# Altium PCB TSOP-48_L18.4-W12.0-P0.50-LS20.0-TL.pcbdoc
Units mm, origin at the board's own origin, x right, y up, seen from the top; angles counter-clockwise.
Board outline 33.53 x 25.28 mm, 2 copper layers (Top Layer, Bottom Layer), stack 0 mm thick; 1 components, 0 nets, 48 pads, 0 vias.
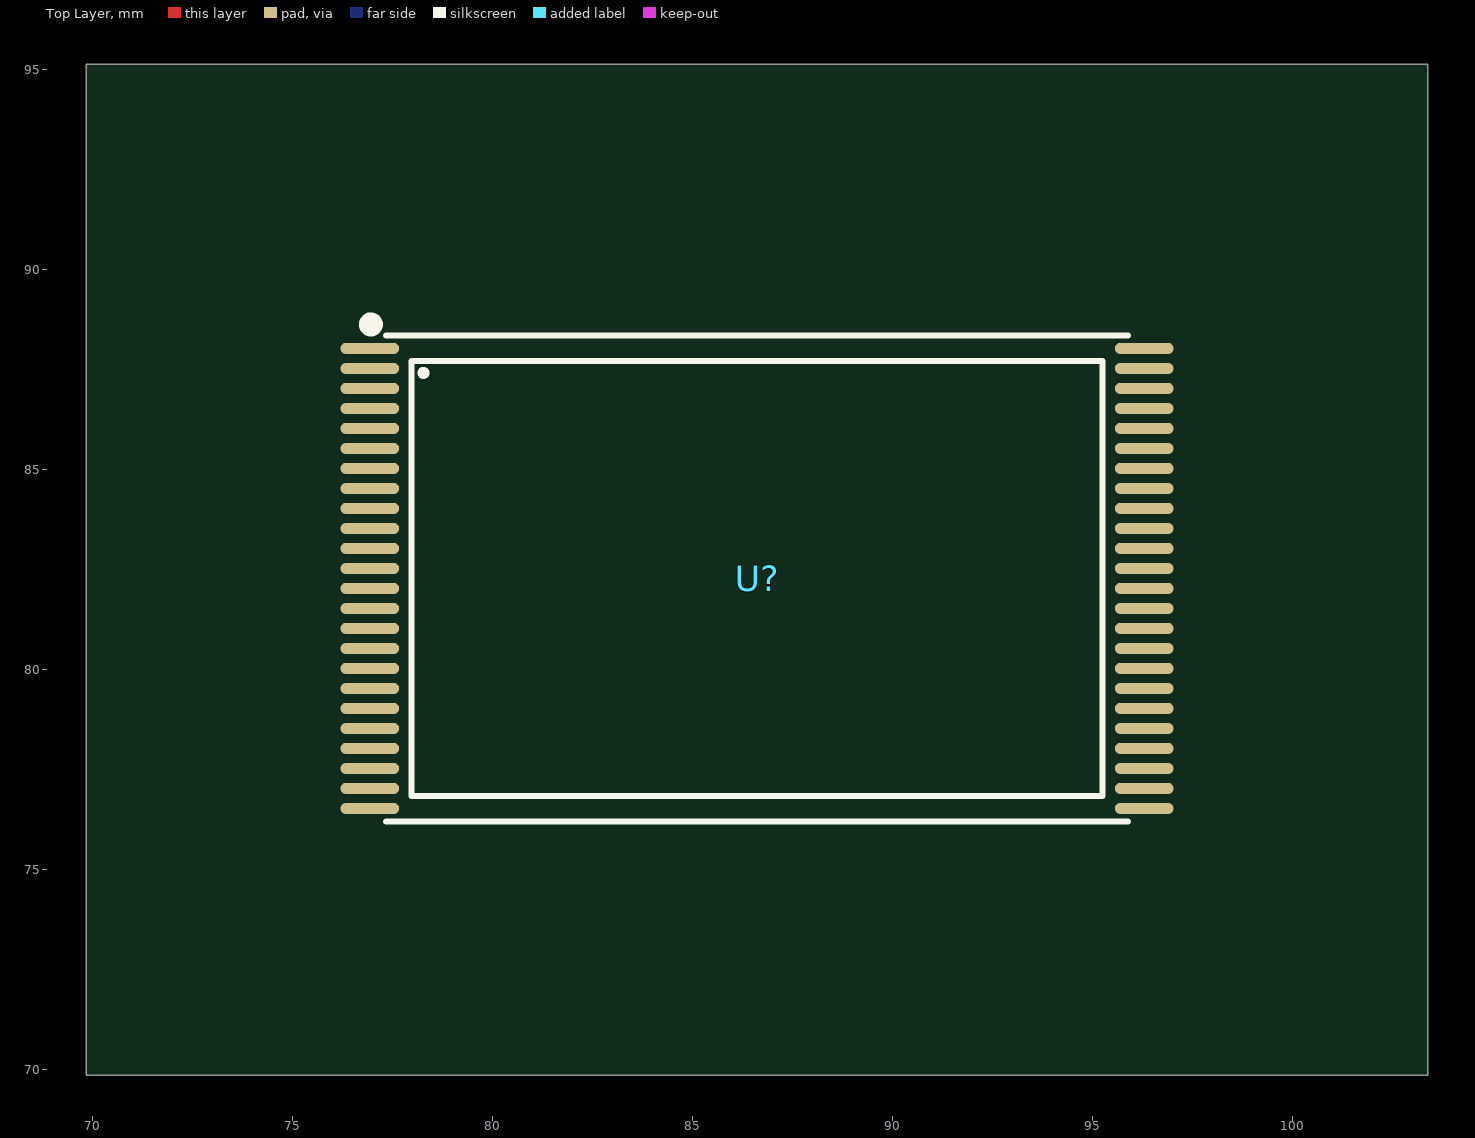
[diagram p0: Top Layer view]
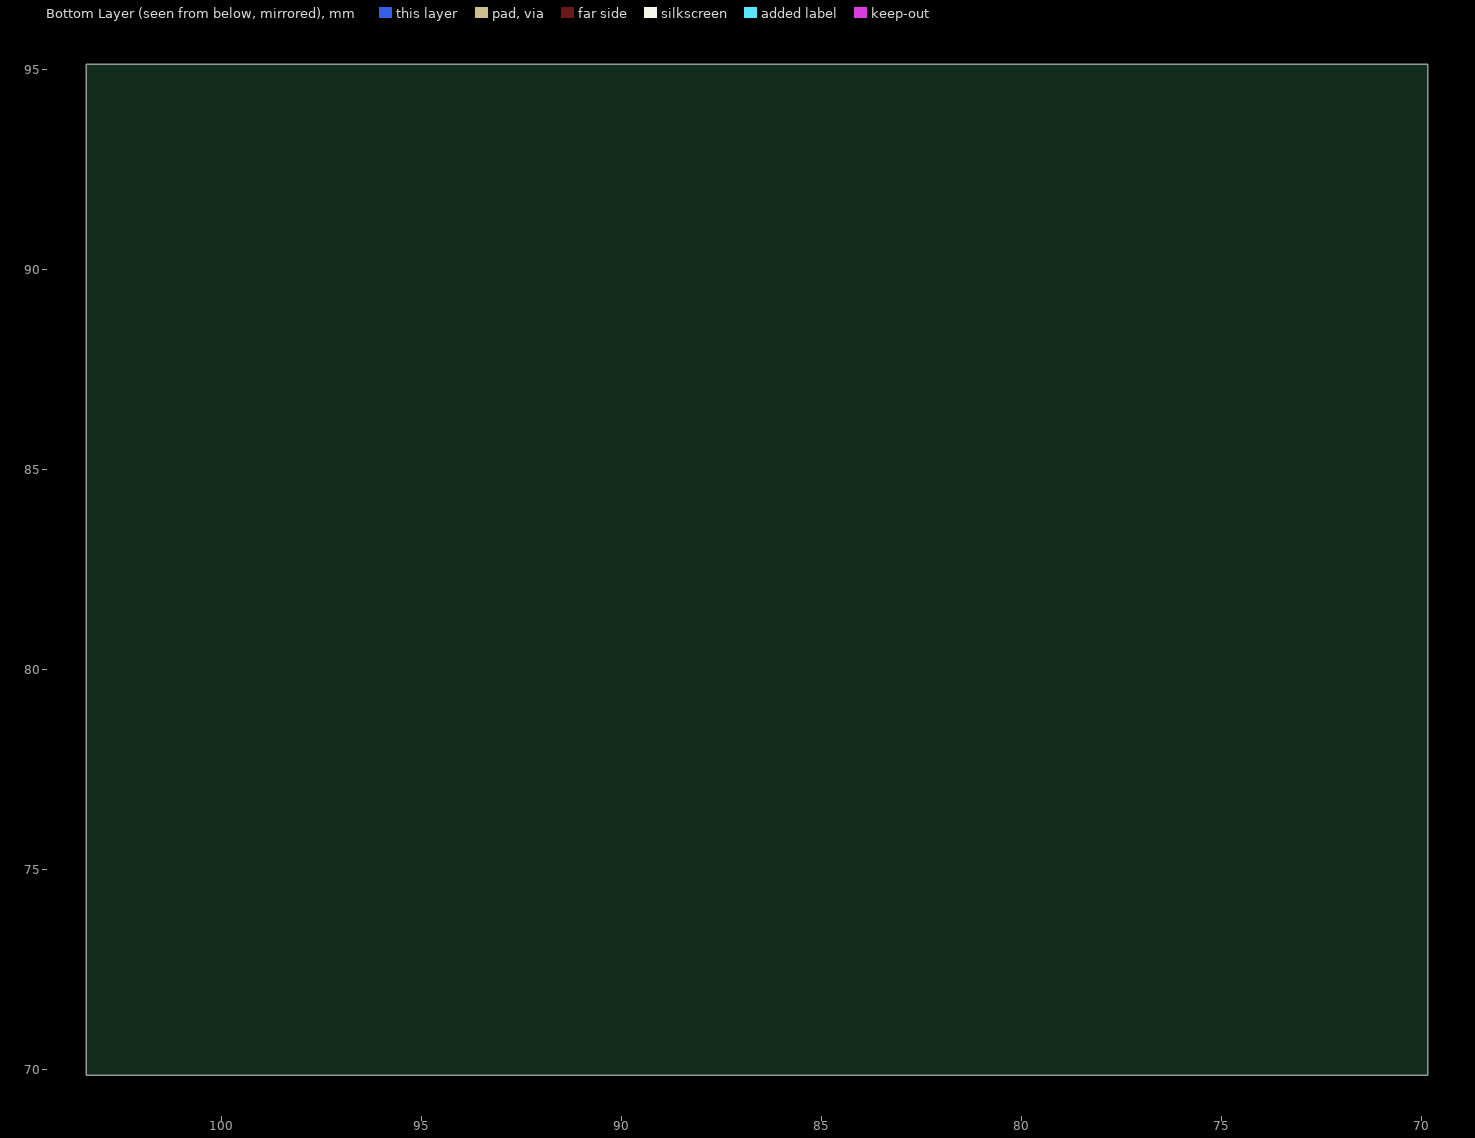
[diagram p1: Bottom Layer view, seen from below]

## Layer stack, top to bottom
Top Layer: signal copper (thickness not stored)
Bottom Layer: signal copper (thickness not stored)

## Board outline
103.38,69.85 69.85,69.85 69.85,95.126 103.38,95.126

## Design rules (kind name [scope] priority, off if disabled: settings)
PasteMaskExpansion "Paste Mask Expansion" [All] p1: expansion=0
SolderMaskExpansion "Solder Mask Expansion" [IsVia] p1: expansion=-25.4 istentingtop=TRUE
SolderMaskExpansion "Solder Mask Expansion" [All] p2: expansion=0.051 istentingtop=FALSE

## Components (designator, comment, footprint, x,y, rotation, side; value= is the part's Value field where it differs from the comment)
U? "" TSOP-48_L18.4-W12.0-P0.50-LS20.0-TL 86.615,82.276 r0 top

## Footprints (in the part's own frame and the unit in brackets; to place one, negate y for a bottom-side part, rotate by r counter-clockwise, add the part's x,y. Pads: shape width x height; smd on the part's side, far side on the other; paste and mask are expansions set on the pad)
TSOP-48_L18.4-W12.0-P0.50-LS20.0-TL [mm]
  oval 1.47x0.28 smd: 1(-9.68,5.75) 2(-9.68,5.25) 3(-9.68,4.75) 4(-9.68,4.25) 5(-9.68,3.75) 6(-9.68,3.25) 7(-9.68,2.75) 8(-9.68,2.25) 9(-9.68,1.75) 10(-9.68,1.25) 11(-9.68,0.75) 12(-9.68,0.25) 13(-9.68,-0.25) 14(-9.68,-0.75) 15(-9.68,-1.25) 16(-9.68,-1.75) 17(-9.68,-2.25) 18(-9.68,-2.75) 19(-9.68,-3.25) 20(-9.68,-3.75) 21(-9.68,-4.25) 22(-9.68,-4.75) 23(-9.68,-5.25) 24(-9.68,-5.75) 25(9.68,-5.75) 26(9.68,-5.25) 27(9.68,-4.75) 28(9.68,-4.25) 29(9.68,-3.75) 30(9.68,-3.25) 31(9.68,-2.75) 32(9.68,-2.25) 33(9.68,-1.75) 34(9.68,-1.25) 35(9.68,-0.75) 36(9.68,-0.25) 37(9.68,0.25) 38(9.68,0.75) 39(9.68,1.25) 40(9.68,1.75) 41(9.68,2.25) 42(9.68,2.75) 43(9.68,3.25) 44(9.68,3.75) 45(9.68,4.25) 46(9.68,4.75) 47(9.68,5.25) 48(9.68,5.75)
  silkscreen extent -9.8,-6.08 9.28,6.5

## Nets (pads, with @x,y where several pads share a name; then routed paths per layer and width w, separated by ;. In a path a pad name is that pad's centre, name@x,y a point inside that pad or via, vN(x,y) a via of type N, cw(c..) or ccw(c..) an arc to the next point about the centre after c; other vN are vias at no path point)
pads on no net: U?.1 U?.2 U?.3 U?.4 U?.5 U?.6 U?.7 U?.8 U?.9 U?.10 U?.11 U?.12 U?.13 U?.14 U?.15 U?.16 U?.17 U?.18 U?.19 U?.20 U?.21 U?.22 U?.23 U?.24 U?.25 U?.26 U?.27 U?.28 U?.29 U?.30 U?.31 U?.32 U?.33 U?.34 U?.35 U?.36 U?.37 U?.38 U?.39 U?.40 U?.41 U?.42 U?.43 U?.44 U?.45 U?.46 U?.47 U?.48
